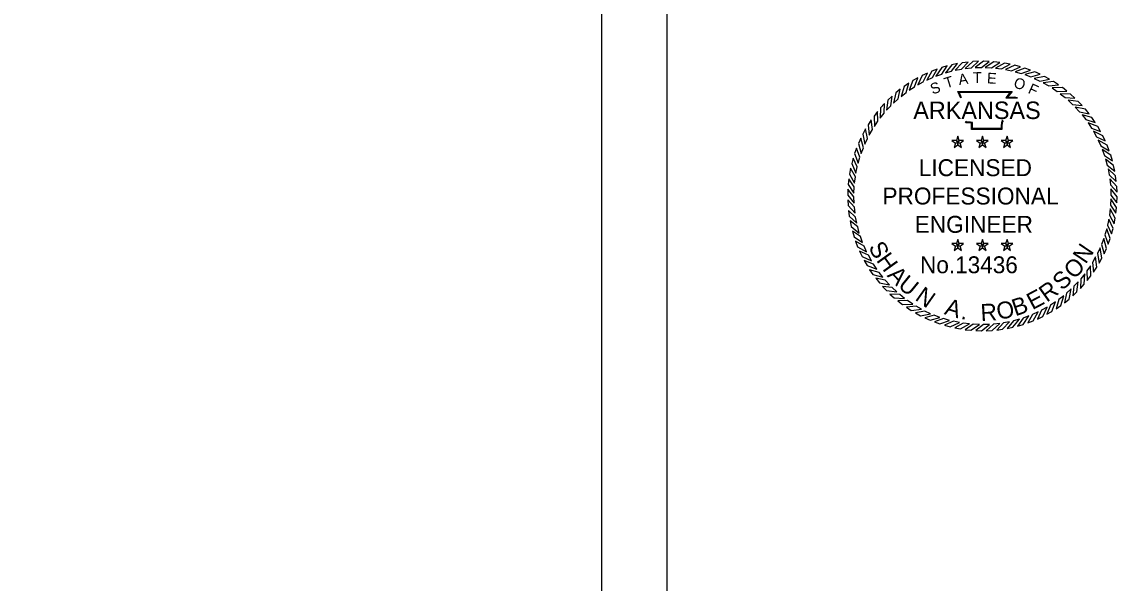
# Model space of a CAD drawing. Extents: x 0 to 38.1, y -1.4 to 22.
# Drawn here: x 28.28 to 37.99, y 10.32 to 15.29 of the extents above; entities that cross this region are included whole.
import ezdxf

# ---------------------------------------------------------------- set-up
doc = ezdxf.new("R2010")
doc.units = 0
doc.layers.add('1', color=7, linetype='Continuous')
doc.layers.add('G-ANNO-SYMB', color=7, linetype='Continuous')

msp = doc.modelspace()

# ---------------------------------------------------------------- linework, layer by layer
at = {"layer": '1'}
msp.add_line((33.4232, 0.5768), (33.4232, 21.4232), dxfattribs=at)
msp.add_lwpolyline([(34, 22), (0, 22), (0, 0), (34, 0)], close=True, dxfattribs=at)
at = {"layer": 'G-ANNO-SYMB'}
for points in [[(36.3928, 14.8726), (36.3449, 14.8543), (36.2998, 14.7747), (36.3503, 14.7976)], [(36.4822, 14.9006), (36.433, 14.8862), (36.3818, 14.8103), (36.434, 14.8291)], [(36.5735, 14.9215), (36.5233, 14.911), (36.4664, 14.8394), (36.5199, 14.854)], [(36.6662, 14.9352), (36.6153, 14.9286), (36.553, 14.8617), (36.6074, 14.8721)], [(36.7597, 14.9415), (36.7085, 14.939), (36.641, 14.8772), (36.6961, 14.8833)], [(36.8534, 14.9405), (36.8021, 14.942), (36.73, 14.8857), (36.7854, 14.8874)], [(36.9467, 14.9322), (36.8957, 14.9377), (36.8194, 14.8872), (36.8748, 14.8846)], [(37.0391, 14.9165), (36.9886, 14.926), (36.9087, 14.8817), (36.9637, 14.8747)], [(37.1299, 14.8937), (37.0804, 14.9071), (36.9972, 14.8692), (37.0515, 14.8579)], [(37.2187, 14.8638), (37.1704, 14.881), (37.0845, 14.8497), (37.1377, 14.8343)], [(37.3049, 14.827), (37.2581, 14.848), (37.1699, 14.8235), (37.2218, 14.804)], [(36.2219, 14.796), (36.1774, 14.7705), (36.1454, 14.6848), (36.1917, 14.7153)], [(36.3059, 14.8377), (36.2595, 14.8157), (36.2209, 14.7328), (36.2694, 14.7595)], [(37.3879, 14.7836), (37.3429, 14.8082), (37.2531, 14.7907), (37.3033, 14.7671)], [(37.4673, 14.7338), (37.4243, 14.7618), (37.3334, 14.7515), (37.3816, 14.724)], [(36.0652, 14.6937), (36.0252, 14.6615), (36.007, 14.5719), (36.048, 14.6092)], [(36.1415, 14.748), (36.0992, 14.719), (36.074, 14.6311), (36.1178, 14.6651)], [(37.5425, 14.6779), (37.5018, 14.7092), (37.4104, 14.706), (37.4563, 14.6749)], [(37.6131, 14.6163), (37.575, 14.6507), (37.4836, 14.6547), (37.5269, 14.6201)], [(35.9263, 14.5681), (35.8919, 14.53), (35.8879, 14.4387), (35.9226, 14.4819)], [(35.9933, 14.6336), (35.956, 14.5984), (35.9448, 14.5076), (35.9828, 14.548)], [(37.6786, 14.5494), (37.6434, 14.5867), (37.5526, 14.5978), (37.593, 14.5599)], [(35.8647, 14.4975), (35.8334, 14.4569), (35.8366, 14.3655), (35.8677, 14.4113)], [(37.7387, 14.4775), (37.7065, 14.5174), (37.6169, 14.5356), (37.6542, 14.4947)], [(37.7929, 14.4011), (37.764, 14.4434), (37.6761, 14.4686), (37.71, 14.4249)], [(35.8088, 14.4223), (35.7808, 14.3793), (35.7912, 14.2885), (35.8186, 14.3366)], [(37.841, 14.3207), (37.8155, 14.3652), (37.7298, 14.3972), (37.7603, 14.3509)], [(35.759, 14.3429), (35.7345, 14.2979), (35.7519, 14.2081), (35.7755, 14.2583)], [(36.5756, 14.224), (36.5879, 14.2408), (36.5756, 14.2785), (36.5634, 14.2408)], [(36.7938, 14.224), (36.806, 14.2408), (36.7938, 14.2785), (36.7816, 14.2408)], [(37.012, 14.224), (37.0242, 14.2408), (37.012, 14.2785), (36.9997, 14.2408)], [(37.8827, 14.2368), (37.8607, 14.2831), (37.7778, 14.3218), (37.8045, 14.2732)], [(35.6788, 14.1737), (35.6616, 14.1254), (35.6929, 14.0395), (35.7083, 14.0927)], [(35.7156, 14.2599), (35.6946, 14.2131), (35.7191, 14.125), (35.7387, 14.1768)], [(36.5756, 14.224), (36.5634, 14.2408), (36.5237, 14.2408), (36.5558, 14.2175)], [(36.5756, 14.224), (36.5558, 14.2175), (36.5436, 14.1798), (36.5756, 14.2031)], [(36.5756, 14.224), (36.5954, 14.2175), (36.6275, 14.2408), (36.5879, 14.2408)], [(36.5756, 14.224), (36.5756, 14.2031), (36.6077, 14.1798), (36.5954, 14.2175)], [(36.7938, 14.224), (36.7816, 14.2408), (36.7419, 14.2408), (36.774, 14.2175)], [(36.7938, 14.224), (36.774, 14.2175), (36.7617, 14.1798), (36.7938, 14.2031)], [(36.7938, 14.224), (36.8136, 14.2175), (36.8457, 14.2408), (36.806, 14.2408)], [(36.7938, 14.224), (36.7938, 14.2031), (36.8259, 14.1798), (36.8136, 14.2175)], [(37.012, 14.224), (36.9997, 14.2408), (36.9601, 14.2408), (36.9922, 14.2175)], [(37.012, 14.224), (36.9922, 14.2175), (36.9799, 14.1798), (37.012, 14.2031)], [(37.012, 14.224), (37.0318, 14.2175), (37.0639, 14.2408), (37.0242, 14.2408)], [(37.012, 14.224), (37.012, 14.2031), (37.044, 14.1798), (37.0318, 14.2175)], [(37.9176, 14.1498), (37.8993, 14.1978), (37.8197, 14.2428), (37.8425, 14.1923)], [(35.6489, 14.085), (35.6355, 14.0354), (35.6735, 13.9522), (35.6847, 14.0065)], [(37.9456, 14.0604), (37.9311, 14.1096), (37.8553, 14.1608), (37.8741, 14.1086)], [(37.9665, 13.9691), (37.9559, 14.0193), (37.8844, 14.0762), (37.899, 14.0228)], [(35.6261, 13.9941), (35.6166, 13.9437), (35.661, 13.8637), (35.6679, 13.9187)], [(37.9802, 13.8764), (37.9736, 13.9273), (37.9067, 13.9897), (37.9171, 13.9352)], [(35.6105, 13.9017), (35.605, 13.8507), (35.6554, 13.7744), (35.658, 13.8298)], [(37.9865, 13.7829), (37.9839, 13.8342), (37.9222, 13.9016), (37.9282, 13.8465)], [(35.6021, 13.8084), (35.6006, 13.7571), (35.6569, 13.6851), (35.6552, 13.7405)], [(37.9855, 13.6892), (37.987, 13.7405), (37.9307, 13.8126), (37.9324, 13.7572)], [(35.6011, 13.7147), (35.6037, 13.6635), (35.6655, 13.5961), (35.6594, 13.6511)], [(37.9772, 13.5959), (37.9826, 13.6469), (37.9322, 13.7232), (37.9296, 13.6678)], [(35.6075, 13.6213), (35.614, 13.5704), (35.6809, 13.508), (35.6705, 13.5624)], [(37.9615, 13.5036), (37.971, 13.554), (37.9266, 13.634), (37.9197, 13.579)], [(35.6211, 13.5286), (35.6317, 13.4784), (35.7032, 13.4214), (35.6886, 13.4749)], [(37.9387, 13.4127), (37.9521, 13.4622), (37.9141, 13.5454), (37.9029, 13.4912)], [(35.642, 13.4372), (35.6565, 13.388), (35.7323, 13.3369), (35.7135, 13.389)], [(37.9088, 13.3239), (37.926, 13.3722), (37.8947, 13.4582), (37.8793, 13.4049)], [(35.67, 13.3478), (35.6883, 13.2999), (35.7679, 13.2548), (35.7451, 13.3054)], [(36.5756, 13.3103), (36.5634, 13.3272), (36.5237, 13.3272), (36.5558, 13.3039)], [(36.5756, 13.3103), (36.5558, 13.3039), (36.5436, 13.2662), (36.5756, 13.2895)], [(36.5756, 13.3103), (36.5879, 13.3272), (36.5756, 13.3649), (36.5634, 13.3272)], [(36.5756, 13.3103), (36.5954, 13.3039), (36.6275, 13.3272), (36.5879, 13.3272)], [(36.5756, 13.3103), (36.5756, 13.2895), (36.6077, 13.2662), (36.5954, 13.3039)], [(36.7938, 13.3103), (36.7816, 13.3272), (36.7419, 13.3272), (36.774, 13.3039)], [(36.7938, 13.3103), (36.774, 13.3039), (36.7617, 13.2662), (36.7938, 13.2895)], [(36.7938, 13.3103), (36.806, 13.3272), (36.7938, 13.3649), (36.7816, 13.3272)], [(36.7938, 13.3103), (36.8136, 13.3039), (36.8457, 13.3272), (36.806, 13.3272)], [(36.7938, 13.3103), (36.7938, 13.2895), (36.8259, 13.2662), (36.8136, 13.3039)], [(37.012, 13.3103), (36.9997, 13.3272), (36.9601, 13.3272), (36.9922, 13.3039)], [(37.012, 13.3103), (36.9922, 13.3039), (36.9799, 13.2662), (37.012, 13.2895)], [(37.012, 13.3103), (37.0242, 13.3272), (37.012, 13.3649), (36.9997, 13.3272)], [(37.012, 13.3103), (37.0318, 13.3039), (37.0639, 13.3272), (37.0242, 13.3272)], [(37.012, 13.3103), (37.012, 13.2895), (37.044, 13.2662), (37.0318, 13.3039)], [(37.872, 13.2377), (37.893, 13.2846), (37.8685, 13.3727), (37.8489, 13.3208)], [(35.7049, 13.2609), (35.7269, 13.2145), (35.8098, 13.1759), (35.7831, 13.2245)], [(37.7788, 13.0754), (37.8068, 13.1183), (37.7965, 13.2092), (37.769, 13.161)], [(37.8286, 13.1547), (37.8532, 13.1998), (37.8357, 13.2895), (37.8121, 13.2394)], [(35.7466, 13.177), (35.7721, 13.1325), (35.8578, 13.1004), (35.8273, 13.1468)], [(37.7229, 13.0002), (37.7542, 13.0408), (37.751, 13.1322), (37.7199, 13.0863)], [(35.7947, 13.0966), (35.8236, 13.0542), (35.9116, 13.029), (35.8776, 13.0728)], [(35.8489, 13.0202), (35.8811, 12.9802), (35.9707, 12.962), (35.9334, 13.003)], [(37.6613, 12.9296), (37.6957, 12.9676), (37.6997, 13.059), (37.665, 13.0157)], [(35.909, 12.9483), (35.9442, 12.911), (36.035, 12.8999), (35.9946, 12.9378)], [(37.5224, 12.804), (37.5624, 12.8362), (37.5806, 12.9258), (37.5396, 12.8885)], [(37.5943, 12.864), (37.6316, 12.8993), (37.6428, 12.99), (37.6048, 12.9496)], [(35.9745, 12.8813), (36.0126, 12.8469), (36.104, 12.8429), (36.0607, 12.8776)], [(36.0451, 12.8197), (36.0858, 12.7884), (36.1772, 12.7916), (36.1313, 12.8228)], [(37.3657, 12.7016), (37.4102, 12.7272), (37.4422, 12.8128), (37.3959, 12.7824)], [(37.4461, 12.7497), (37.4884, 12.7787), (37.5136, 12.8666), (37.4698, 12.8326)], [(36.1203, 12.7639), (36.1633, 12.7358), (36.2542, 12.7462), (36.206, 12.7736)], [(36.1997, 12.7141), (36.2447, 12.6895), (36.3345, 12.7069), (36.2843, 12.7305)], [(37.1948, 12.625), (37.2427, 12.6433), (37.2878, 12.7229), (37.2373, 12.7001)], [(37.2817, 12.66), (37.3281, 12.6819), (37.3667, 12.7648), (37.3182, 12.7381)], [(36.2827, 12.6706), (36.3295, 12.6497), (36.4177, 12.6741), (36.3658, 12.6937)], [(36.3689, 12.6339), (36.4172, 12.6166), (36.5031, 12.6479), (36.4499, 12.6634)], [(36.4577, 12.604), (36.5072, 12.5906), (36.5904, 12.6285), (36.5361, 12.6397)], [(36.5485, 12.5811), (36.599, 12.5717), (36.6789, 12.616), (36.6239, 12.6229)], [(36.8279, 12.5561), (36.8792, 12.5587), (36.9466, 12.6205), (36.8915, 12.6144)], [(36.9214, 12.5625), (36.9723, 12.5691), (37.0346, 12.6359), (36.9802, 12.6255)], [(37.0141, 12.5761), (37.0643, 12.5867), (37.1212, 12.6583), (37.0677, 12.6436)], [(37.1054, 12.597), (37.1546, 12.6115), (37.2058, 12.6873), (37.1536, 12.6685)], [(36.6409, 12.5655), (36.6919, 12.56), (36.7682, 12.6105), (36.7128, 12.6131)], [(36.7342, 12.5571), (36.7855, 12.5557), (36.8576, 12.612), (36.8022, 12.6102)]]:
    msp.add_lwpolyline(points, close=True, dxfattribs=at)
for points in [[(36.6026, 14.6148), (36.5748, 14.6751), (37.0561, 14.6753), (37.0159, 14.6248), (37.0486, 14.6252), (37.0759, 14.6256), (37.1032, 14.6226)], [(36.6096, 14.618), (36.5867, 14.6674), (37.0403, 14.6677), (36.9999, 14.617), (37.0487, 14.6176), (37.0755, 14.618), (37.1024, 14.615)], [(36.9803, 14.4131), (36.9721, 14.4065), (36.9693, 14.3965), (36.9666, 14.3715), (36.9666, 14.3383), (36.698, 14.3383), (36.698, 14.3832), (36.698, 14.3932), (36.6871, 14.3965), (36.6488, 14.3965), (36.642, 14.4068)], [(36.9755, 14.4191), (36.9653, 14.4108), (36.9618, 14.3979), (36.959, 14.3719), (36.959, 14.3459), (36.7056, 14.3459), (36.7056, 14.3832), (36.7056, 14.3988), (36.6882, 14.4041), (36.653, 14.4041), (36.6484, 14.411)]]:
    msp.add_lwpolyline(points, dxfattribs=at)

# ---------------------------------------------------------------- texts
for s, height, rotation, p in [('T', 0.0949, 1.47887, (36.7106, 14.7496)), ('S', 0.0949, 19.77256, (36.352, 14.6464)), ('T', 0.0949, 16.90148, (36.4727, 14.7006)), ('A', 0.0949, 8.67877, (36.588, 14.7307)), ('E', 0.0949, 356.67203, (36.8321, 14.7467)), ('O', 0.0949, 341.2218, (37.0626, 14.7141)), ('F', 0.0949, 335.36282, (37.1905, 14.6641)), ('S', 0.15, 298.16364, (35.7802, 13.2969)), ('N', 0.15, 56.10067, (37.7086, 13.1401)), ('H', 0.15, 305.61905, (35.8486, 13.1793)), ('A', 0.15, 313.44722, (35.9438, 13.0424)), ('O', 0.15, 44.77573, (37.6044, 13.0051)), ('U', 0.15, 320.90262, (36.0373, 12.9446)), ('S', 0.15, 43.48784, (37.5014, 12.9056)), ('N', 0.15, 324.93262, (36.1885, 12.8329)), ('E', 0.15, 27.83149, (37.2367, 12.7372)), ('R', 0.15, 35.65967, (37.3635, 12.8036)), ('A', 0.15, 343.09908, (36.45, 12.7042)), ('O', 0.15, 11.42961, (36.9348, 12.6512)), ('B', 0.15, 18.88501, (37.0852, 12.683)), ('R', 0.15, 3.22866, (36.7813, 12.6415)), ('.', 0.15, 351.30002, (36.5974, 12.6605))]:
    msp.add_text(s, height=height, rotation=rotation, dxfattribs=at).set_placement(p)
for s, height, p in [('ARKANSAS', 0.15494, (36.1814, 14.4304)), ('LICENSED', 0.15, (36.2295, 13.9247)), ('PROFESSIONAL', 0.150001, (35.9081, 13.6738)), ('ENGINEER', 0.15, (36.1938, 13.423)), ('No.13436', 0.14941, (36.2411, 13.0654))]:
    msp.add_text(s, height=height, dxfattribs=at).set_placement(p)

doc.saveas('drawing.dxf')
